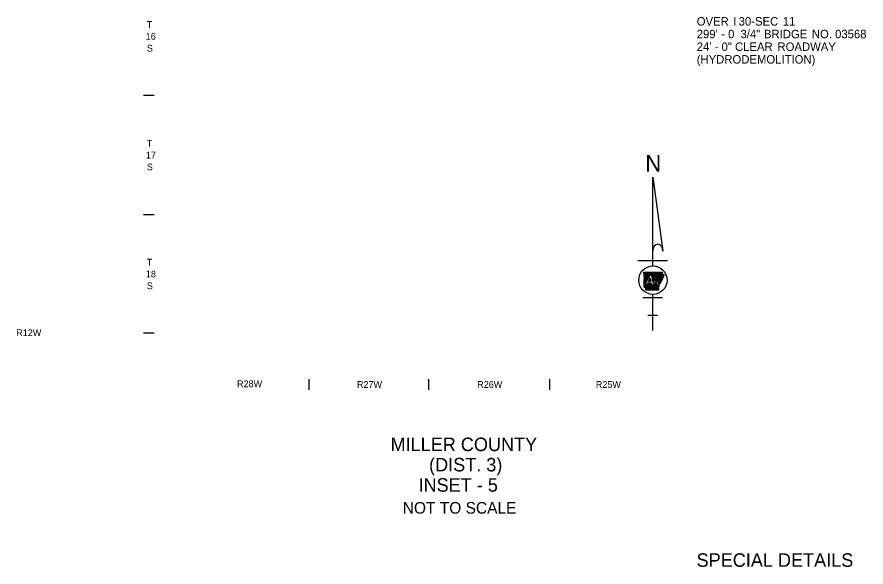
# Model space of a CAD drawing. Extents: x -17668 to 16999, y -17303 to 5867.
# Drawn here: x 9462 to 16999, y -17303 to -12421 of the extents above; entities that cross this region are included whole.
import ezdxf

# ---------------------------------------------------------------- set-up
doc = ezdxf.new("R2010")
doc.units = 0
for name, color, linetype in [('2', 7, 'Continuous'), ('48', 7, 'Continuous'), ('Default', 7, 'Continuous')]:
    doc.layers.add(name, color=color, linetype=linetype)

msp = doc.modelspace()

# ---------------------------------------------------------------- linework, layer by layer
at = {"layer": '48'}
for p, q in [((15105.1, -13843.1), (15196, -14500.1)), ((15105.1, -14631), (15105.1, -13843.1)), ((14973.5, -14582.3), (15236.6, -14582.3)), ((15025.3, -14687.5), (15026.3, -14686.4)), ((15025.6, -14690.5), (15029.8, -14686.4)), ((15026, -14693.6), (15033.3, -14686.4)), ((15026.4, -14696.7), (15036.8, -14686.4)), ((15026.8, -14699.8), (15040.3, -14686.4)), ((15027.2, -14702.9), (15043.7, -14686.4)), ((15027.6, -14706), (15047.2, -14686.4)), ((15028, -14709.1), (15050.7, -14686.4)), ((15028.3, -14712.2), (15054.2, -14686.4)), ((15028.7, -14715.3), (15057.7, -14686.4)), ((15029.1, -14718.4), (15061.1, -14686.4)), ((15029.5, -14721.5), (15064.6, -14686.4)), ((15029.9, -14724.6), (15068.1, -14686.4)), ((15030.3, -14727.7), (15071.6, -14686.4)), ((15030.4, -14762.4), (15106.5, -14686.3)), ((15030.5, -14758.8), (15103, -14686.3)), ((15030.6, -14755.2), (15099.5, -14686.3)), ((15030.7, -14751.6), (15096, -14686.3)), ((15030.7, -14730.8), (15075.1, -14686.4)), ((15030.9, -14748), (15092.5, -14686.4)), ((15031, -14744.4), (15089, -14686.4)), ((15031, -14733.9), (15078.6, -14686.4)), ((15031.1, -14740.8), (15085.5, -14686.4)), ((15031.2, -14737.2), (15082.1, -14686.4)), ((15082.1, -14714.2), (15110, -14686.3)), ((15085.6, -14714.2), (15113.5, -14686.3)), ((15089.1, -14714.2), (15117, -14686.3)), ((15092.6, -14714.2), (15120.5, -14686.2)), ((15094.7, -14715.5), (15124.1, -14686.2)), ((15095.3, -14718.4), (15127.6, -14686.1)), ((15095.9, -14721.2), (15131.1, -14686.1)), ((15096.6, -14724.1), (15134.7, -14686)), ((15097.2, -14727), (15138.2, -14685.9)), ((15097.8, -14729.8), (15141.7, -14685.9)), ((15098.4, -14732.7), (15145.3, -14685.8)), ((15099, -14735.6), (15148.8, -14685.8)), ((15099.6, -14738.5), (15152.4, -14685.7)), ((15100.2, -14741.3), (15155.9, -14685.7)), ((15100.9, -14744.2), (15159.4, -14685.6)), ((15101.5, -14747.1), (15163, -14685.6)), ((15102.1, -14749.9), (15166.5, -14685.5)), ((15102.7, -14752.8), (15170.1, -14685.4)), ((15126.9, -14732.1), (15173.6, -14685.3)), ((15130.4, -14732.1), (15177.2, -14685.3)), ((15133.9, -14732.1), (15180.8, -14685.2)), ((15137.3, -14732.1), (15184.3, -14685.1)), ((15140.8, -14732.1), (15187.9, -14685)), ((15144.3, -14732.1), (15188.7, -14687.7)), ((15147.8, -14732.1), (15190.4, -14689.5)), ((15151.3, -14732.1), (15190.8, -14692.5)), ((15029.5, -14787.6), (15050, -14767.2)), ((15029.7, -14784), (15054.5, -14759.2)), ((15029.8, -14780.4), (15059.1, -14751.1)), ((15029.9, -14776.8), (15063.6, -14743.1)), ((15030, -14773.2), (15068.2, -14735.1)), ((15030.1, -14769.6), (15072.7, -14727.1)), ((15030.3, -14766), (15077.3, -14719)), ((15031.4, -14800), (15080, -14714.2)), ((15067.2, -14766.3), (15083, -14738.2)), ((15067.2, -14766.3), (15089.1, -14766.3)), ((15067.3, -14766.3), (15085.2, -14748.4)), ((15070.8, -14766.3), (15085.8, -14751.3)), ((15071.5, -14758.7), (15084.6, -14745.5)), ((15074.3, -14766.3), (15086.5, -14754.2)), ((15076, -14750.6), (15084, -14742.7)), ((15077.8, -14766.3), (15087.1, -14757)), ((15080, -14714.2), (15094.4, -14714.2)), ((15080.6, -14742.6), (15083.4, -14739.8)), ((15081.3, -14766.3), (15087.7, -14759.9)), ((15084.7, -14766.3), (15088.3, -14762.8)), ((15088.2, -14766.3), (15088.9, -14765.6)), ((15103.3, -14755.7), (15123.1, -14735.9)), ((15103.9, -14758.5), (15122.3, -14740.1)), ((15104.5, -14761.4), (15121.6, -14744.3)), ((15105.2, -14764.3), (15120.9, -14748.6)), ((15105.8, -14767.1), (15120.1, -14752.8)), ((15106.4, -14770), (15119.4, -14757)), ((15107, -14772.9), (15118.7, -14761.2)), ((15107.6, -14775.7), (15117.9, -14765.4)), ((15108.2, -14778.6), (15117.2, -14769.6)), ((15123.7, -14732.1), (15157.5, -14732.1)), ((15128.1, -14779.7), (15135, -14772.7)), ((15128.8, -14775.4), (15131.6, -14772.7)), ((15135.1, -14772.7), (15129.3, -14772.7)), ((15131.1, -14762.5), (15149.4, -14744.2)), ((15131.1, -14762.5), (15145.5, -14762.5)), ((15131.8, -14758.3), (15145.9, -14744.2)), ((15132.5, -14754.1), (15142.4, -14744.2)), ((15133.3, -14749.9), (15139, -14744.2)), ((15134, -14745.7), (15135.5, -14744.2)), ((15134.3, -14744.2), (15150.1, -14744.2)), ((15134.6, -14762.5), (15151.3, -14745.7)), ((15145.2, -14800), (15135.1, -14772.7)), ((15138.1, -14762.5), (15152.5, -14748)), ((15141.5, -14762.5), (15153.2, -14750.9)), ((15145, -14762.5), (15152.9, -14754.7)), ((15149.4, -14771.2), (15160, -14800)), ((15149.7, -14772), (15150.8, -14770.9)), ((15150.6, -14774.5), (15157.3, -14767.9)), ((15151.6, -14777.1), (15190.2, -14738.5)), ((15152.5, -14779.6), (15190.8, -14741.3)), ((15153.5, -14782.2), (15191.5, -14744.1)), ((15154.4, -14784.7), (15192.1, -14746.9)), ((15154.8, -14732.1), (15182.9, -14704)), ((15155.3, -14787.2), (15176.2, -14766.3)), ((15156.3, -14789.8), (15175.8, -14770.2)), ((15157.9, -14732.4), (15182.2, -14708.1)), ((15159.8, -14734), (15185.9, -14708)), ((15161.5, -14735.8), (15189.5, -14707.8)), ((15162.9, -14762.2), (15189.5, -14735.6)), ((15163, -14737.7), (15193.2, -14707.6)), ((15164.3, -14739.9), (15196.9, -14707.4)), ((15165.4, -14742.4), (15200.5, -14707.2)), ((15166, -14755.7), (15197.6, -14724.1)), ((15166.2, -14745), (15203.8, -14707.4)), ((15166.7, -14748), (15205.5, -14709.2)), ((15166.7, -14751.5), (15197.2, -14721)), ((15180.2, -14762.3), (15185.1, -14757.5)), ((15193.7, -14731.5), (15198, -14727.2)), ((15203.9, -14714.3), (15207.1, -14711.1)), ((15028.6, -14816.4), (15045.1, -14800)), ((15028.7, -14812.9), (15041.6, -14800)), ((15028.8, -14809.3), (15038.1, -14800)), ((15028.9, -14805.7), (15034.6, -14800)), ((15029.1, -14802.1), (15031.8, -14799.3)), ((15029.2, -14798.4), (15036.3, -14791.3)), ((15029.3, -14794.8), (15040.9, -14783.3)), ((15029.4, -14791.2), (15045.4, -14775.2)), ((15029.9, -14818.6), (15066.5, -14782)), ((15048.1, -14800), (15031.4, -14800)), ((15032, -14820), (15070, -14782)), ((15034.5, -14821), (15073.5, -14782)), ((15038.7, -14820.3), (15077, -14782)), ((15042.2, -14820.3), (15080.5, -14782)), ((15044.9, -14821), (15084, -14782)), ((15045, -14827.9), (15090.9, -14782)), ((15045, -14824.4), (15087.4, -14782)), ((15045.1, -14831.3), (15092.8, -14783.6)), ((15045.1, -14834.8), (15093.4, -14786.5)), ((15045.1, -14838.3), (15094, -14789.4)), ((15045.1, -14841.8), (15094.6, -14792.2)), ((15045.1, -14845.2), (15095.2, -14795.1)), ((15058.3, -14782), (15048.1, -14800)), ((15048.6, -14845.2), (15095.8, -14798)), ((15052, -14793), (15063.1, -14782)), ((15052.1, -14845.2), (15097.3, -14800)), ((15055.6, -14845.2), (15100.8, -14800)), ((15056.6, -14785), (15059.6, -14782)), ((15092.4, -14782), (15058.3, -14782)), ((15059, -14845.2), (15104.3, -14800)), ((15062.5, -14845.2), (15107.8, -14800)), ((15066, -14845.2), (15111.2, -14800)), ((15069.5, -14845.2), (15114.7, -14800)), ((15073, -14845.2), (15118.2, -14800)), ((15076.4, -14845.2), (15121.7, -14800)), ((15079.9, -14845.2), (15139.8, -14785.3)), ((15083.4, -14845.3), (15140.8, -14787.9)), ((15086.9, -14845.3), (15141.7, -14790.4)), ((15090.3, -14845.3), (15142.6, -14793)), ((15093.8, -14845.3), (15143.6, -14795.5)), ((15124.5, -14800), (15096.3, -14800)), ((15097.3, -14845.3), (15144.5, -14798.1)), ((15100.8, -14845.3), (15146.1, -14800)), ((15104.2, -14845.3), (15149.5, -14800)), ((15107.7, -14845.3), (15153, -14800)), ((15108.8, -14781.5), (15116.5, -14773.9)), ((15109.5, -14784.4), (15115.7, -14778.1)), ((15110.1, -14787.2), (15115, -14782.3)), ((15110.7, -14790.1), (15114.3, -14786.5)), ((15111.2, -14845.3), (15156.5, -14800)), ((15111.3, -14793), (15113.5, -14790.7)), ((15111.9, -14795.8), (15112.8, -14795)), ((15114.7, -14845.3), (15157.7, -14802.3)), ((15118.2, -14845.3), (15157.8, -14805.6)), ((15121.6, -14845.3), (15158, -14809)), ((15125.1, -14796.5), (15138.9, -14782.8)), ((15125.1, -14845.3), (15158.1, -14812.3)), ((15125.9, -14792.3), (15137.9, -14780.3)), ((15126.6, -14788.1), (15137, -14777.7)), ((15127.3, -14783.9), (15136.1, -14775.2)), ((15128.6, -14845.3), (15152.4, -14821.5)), ((15132.1, -14845.3), (15153.5, -14823.9)), ((15135.5, -14845.3), (15154.6, -14826.3)), ((15139, -14845.3), (15155.7, -14828.7)), ((15142.5, -14845.4), (15156.7, -14831.1)), ((15160, -14800), (15145.2, -14800)), ((15146, -14845.4), (15157.6, -14833.7)), ((15149.5, -14845.4), (15156.1, -14838.8)), ((15152.9, -14845.4), (15154.5, -14843.8)), ((15157.2, -14792.3), (15175.4, -14774.1)), ((15158.2, -14794.9), (15168.8, -14784.2)), ((15159.1, -14797.4), (15167.3, -14789.2)), ((15017.4, -14910.2), (15192.8, -14910.2)), ((15105.1, -15202.8), (15105.1, -14883.1)), ((15061.2, -15066), (15148.9, -15066))]:
    msp.add_line(p, q, dxfattribs=at)
for points in [[(15025.1, -14686.4), (15073.2, -14686.4), (15115.3, -14686.3), (15165.1, -14685.5), (15188.1, -14685)], [(15025.1, -14686.4), (15073.2, -14686.4), (15115.3, -14686.3), (15165.1, -14685.5), (15188.1, -14685)], [(15030.4, -14761.1), (15031.3, -14735.7), (15025.1, -14686.4)], [(15028.6, -14816.4), (15031.3, -14735.8), (15025.1, -14686.4)], [(15028.6, -14816.4), (15030.4, -14761.1)], [(15083, -14738.2), (15089.1, -14766.3)], [(15094.4, -14714.2), (15112.3, -14797.7), (15123.7, -14732.1)], [(15129.3, -14772.7), (15124.5, -14800)], [(15131.1, -14762.5), (15134.3, -14744.2)], [(15203.2, -14707.1), (15207.4, -14711.4), (15197, -14719.9), (15198.1, -14728.5), (15189.3, -14734.4), (15192.3, -14747.6), (15185.4, -14753.9), (15184.8, -14760.7), (15176.5, -14763.7), (15175.2, -14776.5), (15169.2, -14782.9), (15166.3, -14792.6), (15157.6, -14800.6), (15158.3, -14814.6), (15152.3, -14821.3), (15157.7, -14833.4), (15154, -14845.4)], [(15181, -14708.2), (15203.6, -14707)], [(15181, -14708.2), (15203.6, -14707.1)], [(15154, -14845.4), (15045.1, -14845.2), (15045, -14821.1)], [(15154, -14845.4), (15045.1, -14845.2), (15045, -14821.2)], [(15096.3, -14800), (15092.4, -14782)]]:
    msp.add_lwpolyline(points, dxfattribs=at)
for centre, major_axis, ratio, start_param, end_param in [((15150.5, -14501.6), (-1.9, 63.2), 0.719778, 4.712385, 7.768526), ((15142.1, -14751.9), (-11.1, 0), 0.999987, 1.887169, 3.90762), ((15144.9, -14749.9), (-21.8, 0), 0.999987, 1.777838, 4.099264)]:
    msp.add_ellipse(centre, major_axis=major_axis, ratio=ratio, start_param=start_param, end_param=end_param, dxfattribs=at)
msp.add_ellipse((15107.1, -14757), major_axis=(126, 0), ratio=0.999976, dxfattribs=at)
for points in [[(15188.1, -14685), (15188.3, -14686.3), (15188.7, -14687), (15188.7, -14688.2), (15189.3, -14688.8), (15190.1, -14689.3), (15190.9, -14690.2), (15191.1, -14691.2), (15190.8, -14692.2), (15190.8, -14693.4), (15190.7, -14694.4), (15190.5, -14695.3), (15189.8, -14696.1), (15189.1, -14696.6), (15188.5, -14697.2), (15188, -14697.9), (15187.3, -14698.6), (15186.5, -14699.3), (15185.8, -14700), (15185.2, -14700.8), (15184.9, -14701.7), (15184.2, -14702.4), (15183.7, -14703), (15183, -14703.8), (15182.6, -14704.6), (15182, -14705.5), (15181.8, -14706.4), (15181.4, -14707.1), (15181.3, -14707.2)], [(15188.1, -14685), (15188.3, -14686.3), (15188.7, -14687), (15188.8, -14688.2), (15189.3, -14688.8), (15190.1, -14689.3), (15190.9, -14690.2), (15191.1, -14691.2), (15190.8, -14692.2), (15190.8, -14693.4), (15190.7, -14694.4), (15190.5, -14695.3), (15189.8, -14696.1), (15189.1, -14696.6), (15188.5, -14697.2), (15188, -14697.9), (15187.2, -14698.6), (15186.5, -14699.3), (15185.8, -14700), (15185.2, -14700.8), (15184.9, -14701.7), (15184.2, -14702.4), (15183.7, -14703), (15183, -14703.8), (15182.6, -14704.6), (15182, -14705.5), (15181.8, -14706.4), (15181.4, -14707.1), (15181.3, -14707.2)], [(15179, -14765.1), (15178, -14765.9), (15177.5, -14766.7), (15174.9, -14766.5), (15174.9, -14767.4), (15174, -14767.9), (15173.2, -14768.5), (15173.6, -14769.2), (15174.5, -14769.9), (15175.4, -14770.4), (15176, -14770.9), (15176.1, -14772.1), (15176.3, -14772.9), (15176.6, -14774), (15176.7, -14774.7), (15176.2, -14775.6), (15175.5, -14775.8), (15174.9, -14775.5), (15174.1, -14775.5), (15173.5, -14776.1), (15173, -14776.9), (15172.6, -14777.8), (15172.3, -14778.5), (15171.9, -14779.2), (15171.3, -14780.1), (15170.5, -14780.3), (15169.5, -14780.5), (15169, -14781.2), (15169.1, -14782.3), (15169.6, -14783), (15170, -14783.9), (15170.3, -14784.7), (15170.2, -14785.7), (15169.8, -14786.5), (15169.2, -14786.9), (15169, -14787.9), (15168.6, -14788.6), (15168.2, -14788.8), (15167.5, -14788.8), (15166.8, -14788.6), (15166.1, -14788.7), (15165.5, -14789), (15164.8, -14788.8), (15164.2, -14788.1), (15163.7, -14787.6), (15163.1, -14787.3), (15162.4, -14787.7), (15162.3, -14788.7), (15162.6, -14789.7), (15162.9, -14791), (15162.6, -14791.9), (15162.5, -14793.2)], [(15191.9, -14735.7), (15192, -14736.5), (15191.5, -14737.4), (15191.3, -14738.4), (15191.4, -14739.3), (15190.5, -14739.8), (15189.6, -14740.4), (15190.1, -14741.1), (15191, -14741.8), (15191.9, -14742.2), (15192.5, -14742.8), (15192.6, -14744), (15192.8, -14744.8), (15193.1, -14745.8), (15193.2, -14746.6), (15192.7, -14747.5), (15192, -14747.6), (15191.4, -14747.4), (15190.6, -14747.4), (15190, -14747.9), (15189.5, -14748.8), (15189.1, -14749.6), (15188.7, -14750.3), (15188.4, -14751.1), (15187.8, -14752), (15187, -14752.1), (15186, -14752.4), (15185.5, -14753), (15185.6, -14754.1), (15186.1, -14754.9), (15186.5, -14755.8), (15186.8, -14756.6), (15186.7, -14757.6), (15186.2, -14758.4), (15185.7, -14758.8), (15185.5, -14759.8), (15185.1, -14760.5), (15184.7, -14760.7), (15184, -14760.7), (15183.2, -14760.5), (15182.6, -14760.6), (15182, -14760.9), (15181.3, -14760.7), (15180.7, -14760), (15180.1, -14759.4), (15179.5, -14759.2), (15178.9, -14759.6), (15178.8, -14760.5), (15179.1, -14761.5), (15179.4, -14762.9), (15179.1, -14763.7), (15179, -14765.1)], [(15203.2, -14707.1), (15203.6, -14707.1), (15204.6, -14708.1), (15205, -14709), (15205.7, -14709.5), (15206.4, -14709.8), (15207, -14710.5), (15207.4, -14711.2), (15207.2, -14711.9), (15206.3, -14711.9), (15205.4, -14712.1), (15204.5, -14712), (15203.8, -14712.7), (15204.4, -14713.4), (15205.3, -14714.2), (15205.6, -14715), (15205.1, -14715.7), (15204.1, -14716.2), (15203.2, -14716.5), (15202.4, -14717.2), (15202, -14717.9), (15201.1, -14718.2), (15200.1, -14718.5), (15199.3, -14718.6), (15198.3, -14718.8), (15197.4, -14719.2), (15197, -14720), (15197.1, -14721.1), (15197.1, -14722.2), (15198.1, -14722.6), (15198.9, -14722.7), (15199.8, -14723.1), (15199.7, -14723.7), (15199.1, -14724.6), (15198.3, -14725.2), (15197.6, -14725.6), (15196.9, -14726.2), (15197.1, -14726.8), (15197.8, -14727.2), (15198.2, -14727.9), (15198.1, -14728.5), (15197.4, -14729), (15196.7, -14728.8), (15196.1, -14728), (15195.4, -14727.8), (15194.9, -14727.6), (15194.2, -14727.9), (15194.2, -14728.8), (15194, -14729.7), (15194.2, -14730.4), (15194.4, -14731.3), (15194.4, -14732.1), (15194.2, -14733.1), (15193.7, -14734.1), (15193.1, -14734.4), (15192.8, -14733.3), (15192.7, -14732.4), (15192.4, -14731.8), (15191.9, -14731.8), (15191.3, -14732.3), (15190.6, -14733), (15189.7, -14733.7), (15189.2, -14734.4), (15189.5, -14735.4), (15190.1, -14735.6), (15190.7, -14735.4), (15190.9, -14734.8), (15191.4, -14734.8), (15191.9, -14735.7)], [(15045, -14821.1), (15045.2, -14821.2), (15044.6, -14820.8), (15043.8, -14820.4), (15042.9, -14820.4), (15041.8, -14820.2), (15040.9, -14820.1), (15040, -14819.5), (15039, -14820.2), (15037.8, -14820.7), (15037.2, -14820.1), (15036.3, -14820.5), (15035.7, -14820.3), (15034.7, -14821), (15033.7, -14820.7), (15033, -14820.9), (15032.1, -14820.9), (15031.9, -14819.9), (15031.1, -14819.8), (15030.3, -14819.3), (15029.8, -14818.3), (15029.4, -14817.5), (15028.6, -14816.4)], [(15045, -14821.2), (15045.1, -14821.2), (15044.6, -14820.8), (15043.8, -14820.4), (15042.9, -14820.4), (15041.8, -14820.2), (15040.9, -14820.1), (15040, -14819.5), (15039, -14820.2), (15037.8, -14820.6), (15037.2, -14820.1), (15036.3, -14820.5), (15035.7, -14820.3), (15034.7, -14821), (15033.7, -14820.7), (15033, -14820.9), (15032.1, -14820.9), (15031.9, -14819.9), (15031.1, -14819.8), (15030.3, -14819.3), (15029.8, -14818.3), (15029.5, -14817.5), (15028.6, -14816.4)], [(15158.5, -14804.4), (15158.2, -14805.1), (15157.9, -14806.3), (15158, -14807.3), (15158.5, -14808.2), (15159.2, -14808.6), (15159.9, -14809.3), (15159.9, -14810.4), (15159.4, -14810.7), (15158.4, -14810.5), (15157.6, -14810.1), (15156.9, -14810.3), (15156, -14810.8), (15155.3, -14810.9), (15155.3, -14812.3), (15156.2, -14813.3), (15157, -14813.3), (15158, -14813.4), (15158.3, -14814.5), (15157.8, -14815.4), (15156.9, -14815.8), (15155.7, -14815.3), (15154.9, -14814.7), (15154.1, -14814.2), (15153.1, -14813.9), (15152.6, -14814), (15152.3, -14815.3), (15152.8, -14816.4), (15153.5, -14817.2), (15154.2, -14818.2), (15154.1, -14819), (15153.6, -14819.2), (15152.7, -14819.4), (15152.1, -14819.7), (15152, -14819.9), (15152.2, -14820.9), (15152.5, -14822), (15152.5, -14822.9), (15152.2, -14823.6), (15151.7, -14824.8), (15151.7, -14825.6), (15152.1, -14825.9), (15152.5, -14825.8), (15153.1, -14825.4), (15153.5, -14824.9), (15153.9, -14824.3), (15154.5, -14823.8), (15155.2, -14824.3), (15155.4, -14825.2), (15155, -14826), (15154.3, -14826.4), (15153.6, -14826.7), (15153, -14827.3), (15153.1, -14828.1), (15153.6, -14828.5), (15154.7, -14828.3), (15155.4, -14827.9), (15155.9, -14827.6), (15156.4, -14827), (15156.6, -14826.5), (15157, -14826), (15157.7, -14825.8), (15158, -14826.3), (15157.9, -14827.3), (15157.5, -14828.3), (15156.9, -14829.1), (15156.3, -14829.6), (15155.5, -14830.8), (15155.7, -14832), (15156, -14832.9), (15156.4, -14833.6), (15157.1, -14833.5), (15157.9, -14833.4), (15158.4, -14833.7), (15158.3, -14834.6), (15157.7, -14835.4), (15157.2, -14836.2), (15156.9, -14837.2), (15157, -14838), (15157, -14838.6), (15156.8, -14839.4), (15156.3, -14839.8), (15155.2, -14839.8), (15154.1, -14839.7), (15153.5, -14840), (15153.6, -14841), (15154.2, -14841.8), (15154.7, -14842.2), (15155.4, -14843), (15155.7, -14843.7), (15155.6, -14844.3), (15155.2, -14844.8), (15154, -14845.4)], [(15158.5, -14804.4), (15158.2, -14805.1), (15157.9, -14806.3), (15158, -14807.3), (15158.5, -14808.2), (15159.2, -14808.6), (15159.9, -14809.3), (15159.9, -14810.4), (15159.4, -14810.7), (15158.4, -14810.5), (15157.6, -14810.1), (15156.9, -14810.3), (15156, -14810.8), (15155.3, -14810.9), (15155.3, -14812.3), (15156.2, -14813.3), (15157, -14813.3), (15158, -14813.4), (15158.3, -14814.5), (15157.8, -14815.4), (15156.9, -14815.8), (15155.7, -14815.3), (15154.9, -14814.7), (15154.1, -14814.2), (15153.1, -14813.9), (15152.6, -14814), (15152.3, -14815.3), (15152.8, -14816.4), (15153.5, -14817.2), (15154.2, -14818.2), (15154.1, -14819), (15153.6, -14819.2), (15152.7, -14819.4), (15152.1, -14819.7), (15152, -14819.9), (15152.2, -14820.9), (15152.5, -14822), (15152.5, -14822.9), (15152.2, -14823.6), (15151.7, -14824.8), (15151.7, -14825.6), (15152.1, -14825.9), (15152.5, -14825.8), (15153.1, -14825.4), (15153.5, -14824.9), (15153.9, -14824.3), (15154.5, -14823.8), (15155.2, -14824.3), (15155.4, -14825.2), (15155, -14826), (15154.3, -14826.4), (15153.6, -14826.7), (15153, -14827.3), (15153.1, -14828.1), (15153.6, -14828.5), (15154.7, -14828.3), (15155.4, -14827.9), (15155.9, -14827.6), (15156.4, -14827), (15156.6, -14826.5), (15157, -14826), (15157.7, -14825.8), (15158, -14826.3), (15157.9, -14827.3), (15157.5, -14828.3), (15156.9, -14829.1), (15156.3, -14829.6), (15155.5, -14830.8), (15155.7, -14832), (15156, -14832.9), (15156.4, -14833.6), (15157.1, -14833.5), (15157.9, -14833.4), (15158.4, -14833.7), (15158.3, -14834.6), (15157.7, -14835.4), (15157.2, -14836.2), (15156.9, -14837.2), (15157, -14838), (15157, -14838.6), (15156.8, -14839.4), (15156.3, -14839.8), (15155.2, -14839.8), (15154.1, -14839.7), (15153.5, -14840), (15153.6, -14841), (15154.2, -14841.8), (15154.7, -14842.2), (15155.4, -14843), (15155.7, -14843.7), (15155.6, -14844.3), (15155.2, -14844.8), (15154, -14845.4)], [(15162.5, -14793.2), (15162.5, -14793.3), (15161.9, -14794), (15162.2, -14795), (15163.4, -14795.4), (15163.9, -14796.4), (15163.9, -14797.3), (15163.6, -14798.5), (15163, -14799.1), (15162, -14799.3), (15161.2, -14799.5), (15161.1, -14800.9), (15160.7, -14801.5), (15160.1, -14801.7), (15159.2, -14801.3), (15158.7, -14801.1), (15158, -14800.8), (15157.2, -14800.3), (15156.5, -14800.4), (15156.7, -14801.7), (15156.8, -14801.7), (15157.5, -14802.7), (15158.2, -14803.5), (15158.5, -14804.4)], [(15162.5, -14793.2), (15162.5, -14793.3), (15161.9, -14794), (15162.2, -14795), (15163.4, -14795.4), (15163.9, -14796.4), (15163.9, -14797.3), (15163.6, -14798.5), (15163, -14799.1), (15162, -14799.3), (15161.2, -14799.5), (15161.1, -14800.9), (15160.7, -14801.5), (15160.1, -14801.7), (15159.2, -14801.3), (15158.7, -14801.1), (15158, -14800.8), (15157.2, -14800.3), (15156.5, -14800.4), (15156.7, -14801.7), (15156.8, -14801.7), (15157.5, -14802.7), (15158.2, -14803.5), (15158.5, -14804.4)]]:
    msp.add_spline(points, degree=3, dxfattribs=at)
at = {"layer": 'Default'}
for p, q in [((10680.3, -13118), (10585.3, -13118)), ((10680.3, -14176.3), (10585.3, -14176.3)), ((10680.3, -15227.4), (10585.3, -15227.4)), ((12051.6, -15635.3), (12051.6, -15730.3)), ((13115.9, -15635.3), (13115.9, -15730.3)), ((14190.2, -15635.3), (14190.2, -15730.3))]:
    msp.add_line(p, q, dxfattribs=at)

# ---------------------------------------------------------------- texts
at = {"layer": '2'}
for s, p in [('T', (10613.2, -12518.2)), ('16', (10604.2, -12623.2)), ('S', (10614.4, -12728.2)), ('T', (10613.2, -13572.1)), ('17', (10605.9, -13677.1)), ('S', (10614.4, -13782.1)), ('T', (10613.2, -14626.9)), ('18', (10605.9, -14731.9)), ('S', (10614.4, -14836.9))]:
    msp.add_text(s, height=60, rotation=360, dxfattribs=at).set_placement(p)
for s, p in [('R12W', (9455, -15253.3)), ('R28W', (11415.1, -15706.6)), ('R27W', (12479.4, -15712.8)), ('R26W', (13547.3, -15712.8)), ('R25W', (14600.2, -15712.8))]:
    msp.add_text(s, height=60, dxfattribs=at).set_placement(p)
at = {"layer": '48'}
for s, height, p in [('N', 146.7, (15039.7, -13793.5)), ('STS 10-03-17', 3.644, (15095.1, -14882)), ('MILLER COUNTY', 120, (12777.8, -16274.2)), ('(DIST. 3)', 120, (13119.8, -16454.2)), ('INSET - 5', 120, (13026.3, -16634.2)), ('NOT TO SCALE', 102.885, (12886.4, -16828.8)), ('SPECIAL DETAILS', 120, (15494.9, -17300.8))]:
    msp.add_text(s, height=height, dxfattribs=at).set_placement(p)
at = {"layer": 'Default'}
for s, p in [('OVER', (15496, -12497.3)), (' I', (15791.6, -12497.3)), (' 30-SEC', (15840.5, -12497.3)), (' 11', (16232.3, -12497.3)), ("299'", (15496, -12609.8)), (' -', (15685.9, -12609.8)), (' 0', (15746.6, -12609.8)), ('  3/4"', (15828.9, -12609.8)), (' BRIDGE', (16065, -12609.8)), (' NO.', (16490.3, -12609.8)), (' 03568', (16696.5, -12609.8)), ("24'", (15496, -12722.3)), (' 0"', (15688.3, -12722.3)), (' CLEAR', (15808, -12722.3)), (' ROADWAY', (16185.1, -12722.3)), (' -', (15627.6, -12722.3)), ('(HYDRODEMOLITION)', (15496, -12834.8))]:
    msp.add_text(s, height=75, dxfattribs=at).set_placement(p)

doc.saveas('drawing.dxf')
